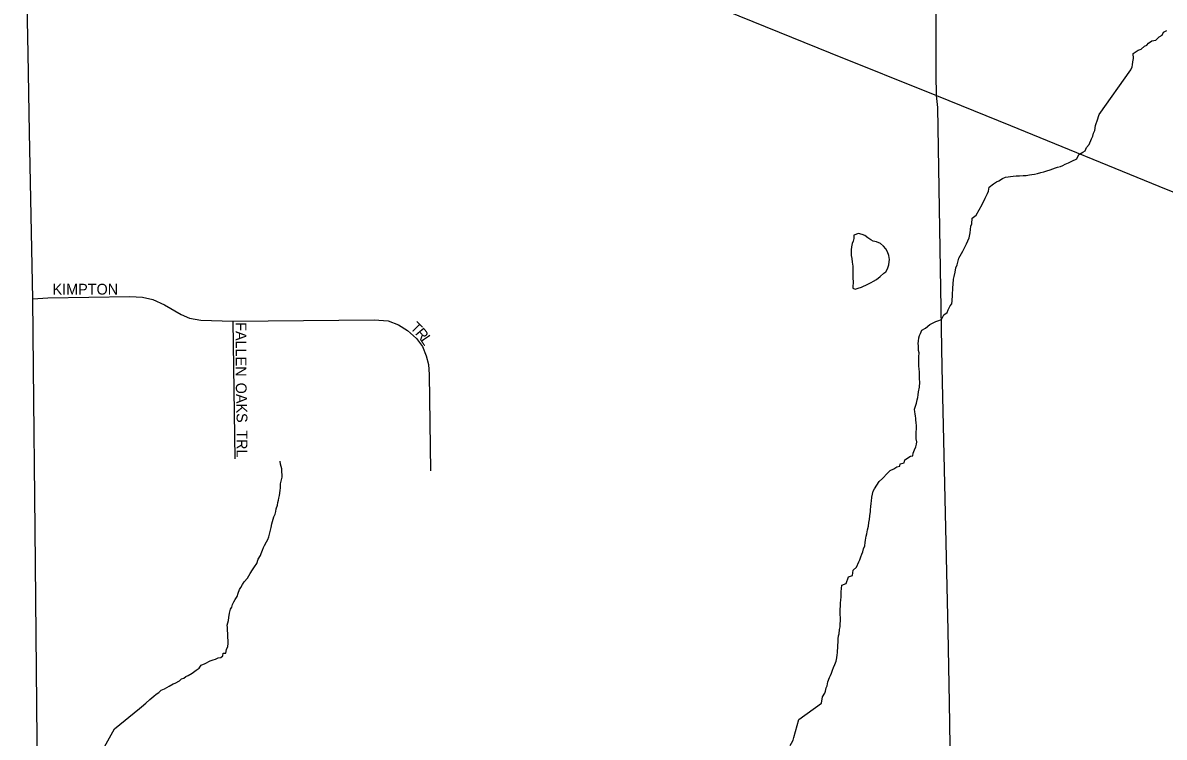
# Model space of a CAD drawing. Extents: x 0 to 34, y 0 to 22.
# Drawn here: x 6.922 to 7.926, y 16.207 to 16.836 of the extents above; entities that cross this region are included whole.
import ezdxf

# ---------------------------------------------------------------- set-up
doc = ezdxf.new("R2010")
doc.units = 0
for name, color, linetype in [('GM_X_County_Road', 7, 'Continuous'), ('GM_X_Minor_Lake', 7, 'Continuous'), ('GM_X_Minor_River', 7, 'Continuous'), ('GM_X_State_Route', 7, 'Continuous'), ('GM_X_Township_Subdivision', 7, 'Continuous'), ('GM_X_Township_Subdivision_Text', 7, 'Continuous'), ('GM_X_US_Route', 7, 'Continuous')]:
    doc.layers.add(name, color=color, linetype=linetype)

msp = doc.modelspace()

# ---------------------------------------------------------------- linework, layer by layer
at = {"layer": 'GM_X_County_Road'}
for points in [[(7.7257, 16.7715), (7.7252, 16.79), (7.7252, 16.8225), (7.7249, 16.8645), (7.723, 16.9497), (7.7227, 17.0471)], [(7.7494, 15.4167), (7.7492, 15.4473), (7.7478, 15.5338), (7.7461, 15.6445), (7.7453, 15.6825), (7.7426, 15.8537), (7.7411, 15.9754), (7.7401, 16.0469), (7.7369, 16.2378), (7.7359, 16.3007), (7.7331, 16.4171), (7.7306, 16.5324), (7.7291, 16.6191), (7.7269, 16.7612), (7.7257, 16.7715)]]:
    msp.add_lwpolyline(points, dxfattribs=at)
at = {"layer": 'GM_X_Minor_Lake'}
for points in [[(7.653, 16.6489), (7.653, 16.6459), (7.6523, 16.6436), (7.6516, 16.6413), (7.6509, 16.6386), (7.6506, 16.6359), (7.6506, 16.6337), (7.6507, 16.631), (7.6511, 16.6283), (7.6516, 16.6249), (7.652, 16.6215), (7.6521, 16.6196), (7.6521, 16.6177), (7.6522, 16.6147), (7.6522, 16.6124), (7.6524, 16.6063), (7.652, 16.6044), (7.6521, 16.6021), (7.654, 16.6014), (7.6566, 16.6022), (7.6597, 16.6031), (7.6615, 16.6039), (7.6634, 16.6047), (7.6657, 16.6059), (7.6683, 16.6071), (7.6702, 16.6082), (7.6728, 16.6098), (7.6762, 16.6125), (7.6792, 16.6153), (7.6811, 16.6165), (7.6825, 16.6191), (7.6836, 16.6226), (7.6839, 16.6253), (7.6842, 16.6275), (7.6838, 16.631), (7.6826, 16.634), (7.681, 16.6366), (7.679, 16.6392), (7.6763, 16.6414), (7.6729, 16.6429), (7.6698, 16.6436), (7.6679, 16.6447), (7.6652, 16.6465), (7.6625, 16.6484), (7.6602, 16.6494), (7.6571, 16.6501), (7.653, 16.6489)], [(7.653, 16.6489), (7.653, 16.6459), (7.6523, 16.6436), (7.6516, 16.6413), (7.6509, 16.6386), (7.6506, 16.6359), (7.6506, 16.6337), (7.6507, 16.631), (7.6511, 16.6283), (7.6516, 16.6249), (7.652, 16.6215), (7.6521, 16.6196), (7.6521, 16.6177), (7.6522, 16.6147), (7.6522, 16.6124), (7.6524, 16.6063), (7.652, 16.6044), (7.6521, 16.6021), (7.654, 16.6014), (7.6566, 16.6022), (7.6597, 16.6031), (7.6615, 16.6039), (7.6634, 16.6047), (7.6657, 16.6059)], [(7.6657, 16.6059), (7.6683, 16.6071), (7.6702, 16.6082), (7.6728, 16.6098), (7.6762, 16.6125), (7.6792, 16.6153), (7.6811, 16.6165), (7.6825, 16.6191), (7.6836, 16.6226), (7.6839, 16.6253), (7.6842, 16.6275), (7.6838, 16.631), (7.6826, 16.634), (7.681, 16.6366), (7.679, 16.6392), (7.6763, 16.6414), (7.6729, 16.6429), (7.6698, 16.6436), (7.6679, 16.6447), (7.6652, 16.6465), (7.6625, 16.6484), (7.6602, 16.6494), (7.6571, 16.6501), (7.653, 16.6489)]]:
    msp.add_lwpolyline(points, dxfattribs=at)
at = {"layer": 'GM_X_Minor_River'}
for points in [[(7.8686, 16.755), (7.8965, 16.7941), (7.8976, 16.7967), (7.898, 16.7986), (7.8983, 16.8013), (7.8987, 16.8043), (7.8986, 16.8085), (7.9028, 16.8116), (7.9054, 16.8124), (7.9085, 16.815), (7.9104, 16.8158), (7.9119, 16.8177), (7.9149, 16.8197), (7.9183, 16.8204), (7.9213, 16.8231), (7.9239, 16.8247), (7.9251, 16.8273), (7.9281, 16.8289)], [(7.7096, 16.5084), (7.7099, 16.511), (7.7106, 16.5152), (7.7109, 16.5194), (7.7108, 16.5225), (7.7108, 16.5247), (7.7107, 16.5266), (7.7107, 16.5285), (7.7103, 16.5308), (7.7102, 16.5339), (7.7101, 16.5369), (7.7101, 16.5396), (7.71, 16.5418), (7.7103, 16.5453), (7.7099, 16.5472), (7.7099, 16.5494), (7.7098, 16.5513), (7.7094, 16.5536), (7.7097, 16.5555), (7.7101, 16.5586), (7.7108, 16.5605), (7.7115, 16.5624), (7.7126, 16.5651), (7.716, 16.567), (7.7197, 16.5702), (7.7227, 16.5718), (7.725, 16.5729), (7.7269, 16.5734), (7.7299, 16.5746), (7.7321, 16.5788), (7.7351, 16.5808), (7.7358, 16.5831), (7.7376, 16.5865), (7.7391, 16.5884), (7.7394, 16.5911), (7.7397, 16.5961), (7.7399, 16.6025), (7.7402, 16.6056), (7.7405, 16.6101), (7.7412, 16.6124), (7.7419, 16.6163), (7.7426, 16.6201), (7.7437, 16.6228), (7.7451, 16.6285), (7.7488, 16.6346), (7.752, 16.6412), (7.7542, 16.6465), (7.7553, 16.6507), (7.7556, 16.6538), (7.7559, 16.6568), (7.7566, 16.6588), (7.7569, 16.6637), (7.7606, 16.6664), (7.7658, 16.6757), (7.7683, 16.6814), (7.7705, 16.6853), (7.7712, 16.6876), (7.7719, 16.691), (7.7757, 16.6938), (7.7783, 16.6957), (7.7805, 16.6965), (7.7835, 16.6985), (7.7862, 16.6997), (7.7885, 16.7001), (7.7907, 16.7005), (7.793, 16.7006), (7.7957, 16.701), (7.7987, 16.7011), (7.8017, 16.7012), (7.8044, 16.7012), (7.8074, 16.7017), (7.8093, 16.7021), (7.8116, 16.7025), (7.8143, 16.7029), (7.8173, 16.7038), (7.8199, 16.7046), (7.8226, 16.7054), (7.8256, 16.7062), (7.8279, 16.707), (7.8301, 16.7079), (7.832, 16.7087), (7.8347, 16.7091), (7.8366, 16.7099), (7.8388, 16.7111), (7.8415, 16.7123), (7.8445, 16.7139), (7.849, 16.7159), (7.8508, 16.7197), (7.8542, 16.7217), (7.8564, 16.7229), (7.8575, 16.7259), (7.8597, 16.7286), (7.8619, 16.7336), (7.863, 16.7359), (7.8637, 16.7386), (7.8648, 16.7409), (7.8655, 16.7451), (7.8658, 16.747), (7.8669, 16.7493), (7.8686, 16.755)], [(7.6045, 16.2228), (7.6245, 16.2371), (7.6255, 16.2428), (7.6273, 16.2459), (7.628, 16.2478), (7.6287, 16.2505), (7.6294, 16.2524), (7.6301, 16.2558), (7.6316, 16.2597), (7.6323, 16.2616), (7.6334, 16.2635), (7.6341, 16.2662), (7.6352, 16.2685), (7.6363, 16.2712), (7.6374, 16.2742), (7.6381, 16.2769), (7.6384, 16.2796), (7.6387, 16.2815), (7.639, 16.2876), (7.6393, 16.2914), (7.6392, 16.2937), (7.6395, 16.2963), (7.6399, 16.2982), (7.6402, 16.302), (7.6409, 16.3043), (7.6409, 16.3066), (7.6412, 16.3097), (7.6411, 16.3119), (7.641, 16.3154), (7.641, 16.3173), (7.641, 16.3195), (7.6413, 16.3226), (7.6412, 16.3249), (7.6415, 16.3283), (7.6419, 16.3302), (7.6418, 16.3329), (7.6418, 16.3351), (7.6424, 16.3408), (7.6462, 16.3425), (7.6483, 16.3482), (7.6517, 16.3494), (7.6524, 16.354), (7.6554, 16.3567), (7.6572, 16.3613), (7.6583, 16.3632), (7.659, 16.3659), (7.6601, 16.3682), (7.6608, 16.3701), (7.6615, 16.3728), (7.6626, 16.3755), (7.6629, 16.3785), (7.6632, 16.3804), (7.6639, 16.3839), (7.6643, 16.3862), (7.665, 16.3896), (7.6657, 16.3927), (7.666, 16.3961), (7.6667, 16.3988), (7.667, 16.4018), (7.6677, 16.4056), (7.6676, 16.4075), (7.6679, 16.4098), (7.6683, 16.4129), (7.6686, 16.4148), (7.6689, 16.4182), (7.6699, 16.4235), (7.671, 16.4255), (7.6751, 16.432), (7.6781, 16.4347), (7.6825, 16.4394), (7.6848, 16.4417), (7.6882, 16.4433), (7.6908, 16.4449), (7.6934, 16.4457), (7.6938, 16.4476), (7.6972, 16.4484), (7.6979, 16.4511), (7.7028, 16.4543), (7.7047, 16.4547), (7.705, 16.457), (7.7064, 16.46), (7.7075, 16.4627), (7.7079, 16.465), (7.7082, 16.4669), (7.7078, 16.4696), (7.7077, 16.4719), (7.7077, 16.4741), (7.7076, 16.476), (7.708, 16.4779), (7.7079, 16.481), (7.7078, 16.484), (7.7074, 16.4859), (7.7074, 16.4878), (7.707, 16.4897), (7.7069, 16.4916), (7.7065, 16.4935), (7.7064, 16.4958), (7.7079, 16.5011), (7.7086, 16.5038), (7.7093, 16.5061), (7.7096, 16.5084)], [(7.0031, 16.2144), (7.025, 16.2325), (7.0269, 16.234), (7.0306, 16.2372), (7.034, 16.2403), (7.0359, 16.2418), (7.0377, 16.2434), (7.0396, 16.2449), (7.0419, 16.2465), (7.0441, 16.2485), (7.0471, 16.2497), (7.049, 16.2508), (7.0512, 16.252), (7.0546, 16.254), (7.0565, 16.2548), (7.0603, 16.2568), (7.0621, 16.2584), (7.064, 16.2592), (7.0659, 16.2607), (7.0678, 16.2615), (7.0712, 16.2635), (7.0749, 16.2662), (7.0775, 16.2678), (7.0794, 16.2705), (7.0828, 16.2721), (7.0873, 16.2745), (7.0899, 16.2753), (7.0918, 16.2757), (7.0941, 16.2769), (7.0964, 16.2773), (7.0982, 16.2789), (7.0986, 16.2812), (7.1008, 16.2812), (7.1015, 16.2843), (7.1026, 16.287), (7.1029, 16.2896), (7.1029, 16.2923), (7.1028, 16.295), (7.1028, 16.298), (7.1023, 16.3014), (7.1023, 16.3037), (7.1022, 16.3056), (7.1033, 16.3098), (7.1036, 16.3125), (7.1043, 16.3163), (7.105, 16.3197), (7.1061, 16.3216), (7.1068, 16.3239), (7.1079, 16.3262), (7.109, 16.3282), (7.1108, 16.3309), (7.1119, 16.3339), (7.113, 16.337), (7.1141, 16.3389), (7.1155, 16.3416), (7.117, 16.3439), (7.12, 16.347), (7.1222, 16.3512), (7.1244, 16.3543), (7.1262, 16.357), (7.1281, 16.3601), (7.1295, 16.3639), (7.1314, 16.367), (7.1321, 16.3689), (7.1332, 16.3716), (7.1339, 16.3739), (7.135, 16.3758), (7.1368, 16.3789), (7.1379, 16.3812), (7.1386, 16.3835), (7.1407, 16.3915), (7.1414, 16.395), (7.1421, 16.3969), (7.1432, 16.4011), (7.1443, 16.4034), (7.145, 16.4057), (7.1453, 16.408), (7.1464, 16.4114), (7.1467, 16.4137), (7.1471, 16.4156), (7.1474, 16.4175), (7.1481, 16.4198), (7.1484, 16.4217), (7.1488, 16.4244), (7.1491, 16.4263), (7.149, 16.4301), (7.1497, 16.4324), (7.1504, 16.4358), (7.1504, 16.4377), (7.1503, 16.4408), (7.1503, 16.4431), (7.149, 16.4472), (7.1486, 16.4499)], [(7.5969, 16.1999), (7.598, 16.2019), (7.5995, 16.2046), (7.6002, 16.2069), (7.6045, 16.2228)], [(6.9942, 16.1988), (7.0031, 16.2144)]]:
    msp.add_lwpolyline(points, dxfattribs=at)
at = {"layer": 'GM_X_State_Route'}
msp.add_lwpolyline([(6.9601, 14.3385), (6.9588, 14.4363), (6.9583, 14.5087), (6.9569, 14.6447), (6.9545, 14.8525), (6.9526, 15.0617), (6.9494, 15.2806), (6.9469, 15.4082), (6.945, 15.4974), (6.9426, 15.6618), (6.9415, 15.7144), (6.9391, 15.8578), (6.9382, 15.9358), (6.9378, 15.962), (6.9363, 16.1152), (6.9355, 16.1742), (6.9333, 16.3902), (6.932, 16.532), (6.9312, 16.5929), (6.9284, 16.739), (6.9273, 16.8086), (6.9244, 16.9544), (6.9225, 17.0291)], dxfattribs=at)
at = {"layer": 'GM_X_Township_Subdivision'}
for points in [[(6.9312, 16.5929), (6.9445, 16.5937), (7.0165, 16.5948), (7.0276, 16.5942), (7.0368, 16.5921), (7.0469, 16.5874), (7.0617, 16.5789), (7.0691, 16.5757), (7.0789, 16.5739), (7.1072, 16.5731), (7.2314, 16.5744), (7.2435, 16.5733), (7.2528, 16.5699), (7.2607, 16.5649), (7.2684, 16.558), (7.2737, 16.5508), (7.2771, 16.5426), (7.279, 16.535), (7.2798, 16.5262), (7.2808, 16.4415)], [(7.1072, 16.5731), (7.1088, 16.4521)]]:
    msp.add_lwpolyline(points, dxfattribs=at)
at = {"layer": 'GM_X_US_Route'}
for points in [[(6.9225, 17.0291), (7.0075, 17.0296), (7.0433, 17.0299), (7.0624, 17.0294), (7.0742, 17.0282), (7.094, 17.0245), (7.1153, 17.0189), (7.1643, 16.999), (7.2028, 16.9834), (7.3331, 16.9309), (7.4158, 16.8972), (7.6321, 16.8092), (7.7257, 16.7715), (7.7905, 16.7451)], [(7.7905, 16.7451), (7.921, 16.6919), (8.1911, 16.5828), (8.4468, 16.4792), (8.5967, 16.4181), (8.642, 16.3998)]]:
    msp.add_lwpolyline(points, dxfattribs=at)

# ---------------------------------------------------------------- texts
at = {"layer": 'GM_X_Township_Subdivision_Text'}
for s, rotation, p in [('KIMPTON', 0, (6.9486, 16.5965)), ('T', 314.6909, (7.2623, 16.5668)), ('FALLEN', 270, (7.1096, 16.5722)), ('R', 310.1009, (7.2669, 16.5622)), ('L', 304.175, (7.2716, 16.5567)), ('OAKS', 271.5067, (7.1096, 16.5189)), ('TRL', 270, (7.1104, 16.4772))]:
    msp.add_text(s, height=0.00947, rotation=rotation, dxfattribs=at).set_placement(p)

doc.saveas('drawing.dxf')
